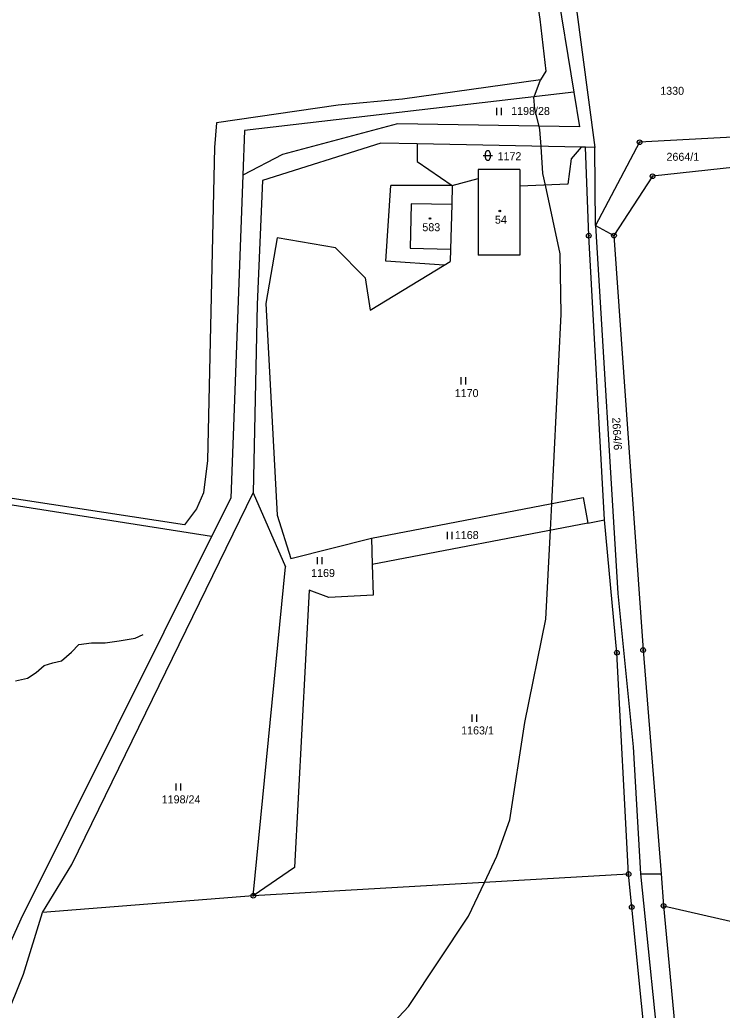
# Model space of a CAD drawing. Extents: x -439246 to -433691, y -1130252 to -1121148.
# Drawn here: x -438121.2 to -437972.2, y -1123253.1 to -1123042.9 of the extents above; entities that cross this region are included whole.
import ezdxf

# ---------------------------------------------------------------- set-up
doc = ezdxf.new("R2010")
doc.units = 0
for name, color, linetype in [('Vrstva 1', 7, 'Continuous'), ('Vrstva 18', 7, 'Continuous'), ('Vrstva 19', 7, 'Continuous'), ('Vrstva 24', 7, 'Continuous'), ('Vrstva 25', 7, 'Continuous'), ('Vrstva 3', 7, 'Continuous'), ('Vrstva 37', 7, 'Continuous'), ('Vrstva 4', 7, 'Continuous'), ('Vrstva 52', 7, 'Continuous'), ('Vrstva 6', 7, 'Continuous')]:
    doc.layers.add(name, color=color, linetype=linetype)

msp = doc.modelspace()

# ---------------------------------------------------------------- linework, layer by layer
at = {"layer": 'Vrstva 1'}
for points in [[(-438007.56, -1123034.35), (-438003.7, -1123058.22)], [(-438003.26, -1123039.6), (-437999.24, -1123069.97)], [(-438003.7, -1123058.22), (-438073.55, -1123066.39)], [(-438003.7, -1123058.22), (-438002.5, -1123065.62)], [(-438073.55, -1123066.39), (-438073.91, -1123075.87)], [(-438041.09, -1123064.97), (-438065.47, -1123071.43)], [(-438002.5, -1123065.62), (-438041.09, -1123064.97)], [(-437989.73, -1123068.85), (-437999.07, -1123086.53)], [(-437962.08, -1123067.39), (-437989.73, -1123068.85)], [(-438044.65, -1123069.05), (-438069.76, -1123077)], [(-438036.94, -1123069.21), (-438044.65, -1123069.05)], [(-438036.94, -1123069.21), (-438036.94, -1123072.93)], [(-438002.12, -1123069.91), (-438036.94, -1123069.21)], [(-438002.12, -1123069.91), (-438004.29, -1123072.36)], [(-438001.21, -1123069.93), (-438002.12, -1123069.91)], [(-438000.51, -1123088.7), (-438001.21, -1123069.93)], [(-437999.24, -1123069.97), (-438001.21, -1123069.93)], [(-437999.07, -1123086.53), (-437999.24, -1123069.97)], [(-438065.47, -1123071.43), (-438073.91, -1123075.87)], [(-438036.94, -1123072.93), (-438029.52, -1123078.04)], [(-438004.29, -1123072.36), (-438004.95, -1123077.74)], [(-438015.13, -1123074.65), (-438024.02, -1123074.65)], [(-438024.02, -1123074.65), (-438024.02, -1123076.55)], [(-438015.13, -1123074.65), (-438015.13, -1123078.21)], [(-437963.49, -1123073.53), (-437986.99, -1123076.08)], [(-438073.91, -1123075.87), (-438076.5, -1123144.41)], [(-438069.76, -1123077), (-438070.85, -1123103.32)], [(-438029.52, -1123078.04), (-438024.02, -1123076.55)], [(-438024.02, -1123076.55), (-438024.02, -1123092.83)], [(-437986.99, -1123076.08), (-437995.17, -1123088.69)], [(-438043.6, -1123094.13), (-438042.5, -1123078.06)], [(-438029.52, -1123078.04), (-438042.5, -1123078.06)], [(-438029.52, -1123078.04), (-438029.61, -1123082.11)], [(-438004.95, -1123077.74), (-438015.13, -1123078.21)], [(-438015.13, -1123078.21), (-438015.13, -1123092.83)], [(-438029.61, -1123082.11), (-438029.83, -1123091.54)], [(-438066.62, -1123089.14), (-438069.06, -1123103.08)], [(-438054.29, -1123091.3), (-438066.62, -1123089.14)], [(-437997.17, -1123149.03), (-438000.51, -1123088.7)], [(-437995.17, -1123088.69), (-437988.99, -1123176.69)], [(-438054.29, -1123091.3), (-438047.95, -1123097.67)], [(-438029.83, -1123091.54), (-438029.9, -1123094.2)], [(-438031.18, -1123094.98), (-438043.6, -1123094.13)], [(-438015.13, -1123092.83), (-438024.02, -1123092.83)], [(-438046.88, -1123104.5), (-438031.18, -1123094.98)], [(-438031.18, -1123094.98), (-438029.9, -1123094.2)], [(-438047.95, -1123097.67), (-438046.88, -1123104.5)], [(-438070.85, -1123103.32), (-438071.7, -1123143.28)], [(-438069.06, -1123103.08), (-438066.6, -1123148.04)], [(-438080.56, -1123152.59), (-438154.88, -1123140.9)], [(-438110.23, -1123222.16), (-438071.7, -1123143.28)], [(-438076.5, -1123144.41), (-438080.56, -1123152.59)], [(-438071.7, -1123143.28), (-438064.88, -1123158.97)], [(-438046.65, -1123152.95), (-438001.73, -1123144.31)], [(-438001.73, -1123144.31), (-438000.69, -1123149.71)], [(-438066.6, -1123148.04), (-438063.7, -1123157.2)], [(-438000.69, -1123149.71), (-438046.48, -1123158.51)], [(-438000.69, -1123149.71), (-437997.17, -1123149.03)], [(-437994.55, -1123177.24), (-437997.17, -1123149.03)], [(-438080.56, -1123152.59), (-438121.05, -1123233.8)], [(-438063.7, -1123157.2), (-438046.65, -1123152.95)], [(-438046.65, -1123152.95), (-438046.48, -1123158.51)], [(-438071.7, -1123228.84), (-438064.88, -1123158.97)], [(-438046.48, -1123158.51), (-438046.28, -1123165.02)], [(-438059.84, -1123163.93), (-438062.95, -1123222.85)], [(-438055.66, -1123165.52), (-438059.84, -1123163.93)], [(-438046.28, -1123165.02), (-438055.66, -1123165.52)], [(-437992.08, -1123224.24), (-437994.55, -1123177.24)], [(-437988.99, -1123176.69), (-437985.19, -1123224.15)], [(-438116.42, -1123232.41), (-438110.23, -1123222.16)], [(-438062.95, -1123222.85), (-438071.7, -1123228.84)], [(-437992.08, -1123224.24), (-438071.7, -1123228.84)], [(-437991.41, -1123231.23), (-437992.08, -1123224.24)], [(-437985.19, -1123224.15), (-437984.64, -1123230.98)], [(-438071.7, -1123228.84), (-438116.42, -1123232.41)], [(-438120.43, -1123245.5), (-438116.42, -1123232.41)], [(-437983.13, -1123313.75), (-437991.41, -1123231.23)], [(-437984.64, -1123230.98), (-437976.9, -1123313.79)], [(-437984.64, -1123230.98), (-437957.14, -1123237.29)], [(-438121.05, -1123233.8), (-438129.19, -1123251.89)], [(-438124.36, -1123255.18), (-438120.43, -1123245.5)]]:
    msp.add_lwpolyline(points, dxfattribs=at)
at = {"layer": 'Vrstva 24'}
for centre, radius in [((-437989.73, -1123068.85), 0.5), ((-437989.73, -1123068.85), 0.1), ((-437986.99, -1123076.08), 0.5), ((-437986.99, -1123076.08), 0.1), ((-438000.51, -1123088.7), 0.5), ((-438000.51, -1123088.7), 0.1), ((-437995.17, -1123088.69), 0.5), ((-437995.17, -1123088.69), 0.1), ((-437994.55, -1123177.24), 0.5), ((-437994.55, -1123177.24), 0.1), ((-437988.99, -1123176.69), 0.5), ((-437988.99, -1123176.69), 0.1), ((-437992.08, -1123224.24), 0.5), ((-437992.08, -1123224.24), 0.1), ((-438071.7, -1123228.84), 0.5), ((-438071.7, -1123228.84), 0.1), ((-437991.41, -1123231.23), 0.5), ((-437984.64, -1123230.98), 0.5), ((-437991.41, -1123231.23), 0.1), ((-437984.64, -1123230.98), 0.1)]:
    msp.add_circle(centre, radius, dxfattribs=at)
at = {"layer": 'Vrstva 25'}
for p, q in [((-438020.02, -1123063.08), (-438020.02, -1123061.58)), ((-438019.02, -1123063.08), (-438019.02, -1123061.58)), ((-438022.96, -1123071.68), (-438020.96, -1123071.68)), ((-438022.46, -1123072.18), (-438022.46, -1123071.18)), ((-438021.46, -1123071.18), (-438021.46, -1123072.18)), ((-438027.63, -1123120.27), (-438027.63, -1123118.77)), ((-438026.63, -1123120.27), (-438026.63, -1123118.77)), ((-438030.47, -1123153.1), (-438030.47, -1123151.6)), ((-438029.47, -1123153.1), (-438029.47, -1123151.6)), ((-438058.11, -1123158.46), (-438058.11, -1123156.96)), ((-438057.11, -1123158.46), (-438057.11, -1123156.96)), ((-438025.29, -1123191.88), (-438025.29, -1123190.38)), ((-438024.29, -1123191.88), (-438024.29, -1123190.38)), ((-438088.04, -1123206.52), (-438088.04, -1123205.02)), ((-438087.04, -1123206.52), (-438087.04, -1123205.02))]:
    msp.add_line(p, q, dxfattribs=at)
for centre in [(-438019.39, -1123083.45), (-438034.21, -1123085.05)]:
    msp.add_circle(centre, 0.175, dxfattribs=at)
for centre, start, end in [((-438021.96, -1123071.18), 0, 180), ((-438021.96, -1123072.18), 180, 0)]:
    msp.add_arc(centre, 0.5, start, end, dxfattribs=at)
at = {"layer": 'Vrstva 3'}
for points in [[(-438015.13, -1123074.65), (-438024.02, -1123074.65)], [(-438024.02, -1123074.65), (-438024.02, -1123076.55)], [(-438015.13, -1123074.65), (-438015.13, -1123078.21)], [(-438024.02, -1123076.55), (-438024.02, -1123092.83)], [(-438015.13, -1123078.21), (-438015.13, -1123092.83)], [(-438038.22, -1123081.91), (-438038.44, -1123091.34)], [(-438029.61, -1123082.11), (-438038.22, -1123081.91)], [(-438029.61, -1123082.11), (-438029.83, -1123091.54)], [(-438038.44, -1123091.34), (-438029.83, -1123091.54)], [(-438015.13, -1123092.83), (-438024.02, -1123092.83)]]:
    msp.add_lwpolyline(points, dxfattribs=at)
at = {"layer": 'Vrstva 37'}
for centre in [(-438019.39, -1123083.45), (-438034.21, -1123085.05)]:
    msp.add_circle(centre, 0.175, dxfattribs=at)
at = {"layer": 'Vrstva 4'}
for points in [[(-438038.22, -1123081.91), (-438038.44, -1123091.34)], [(-438029.61, -1123082.11), (-438038.22, -1123081.91)], [(-438038.44, -1123091.34), (-438029.83, -1123091.54)], [(-438096.78, -1123174.17), (-438095.03, -1123173.38)], [(-438110.25, -1123177.13), (-438108.73, -1123175.5)], [(-438108.73, -1123175.5), (-438106.01, -1123175.16)], [(-438106.01, -1123175.16), (-438103.14, -1123175.16)], [(-438103.14, -1123175.16), (-438100.13, -1123174.69)], [(-438100.13, -1123174.69), (-438096.78, -1123174.17)], [(-438112.41, -1123178.99), (-438110.25, -1123177.13)], [(-438117.75, -1123181.46), (-438116.05, -1123179.92)], [(-438116.05, -1123179.92), (-438114.2, -1123179.4)], [(-438114.2, -1123179.4), (-438112.41, -1123178.99)], [(-438119.61, -1123182.61), (-438117.75, -1123181.46)], [(-438122.14, -1123183.19), (-438119.61, -1123182.61)]]:
    msp.add_lwpolyline(points, dxfattribs=at)
at = {"layer": 'Vrstva 52'}
for points in [[(-438043.8, -1122847.97), (-438041.99, -1122856.04), (-438041.99, -1122859.45), (-438039.43, -1122869.67), (-438026.86, -1122932.75), (-438025.58, -1122944.68), (-438023.24, -1122957.46), (-438022.39, -1122967.69), (-438020.55, -1122978.34), (-438018.12, -1122992.41), (-438017.27, -1123001.78), (-438010.88, -1123042.7), (-438009.6, -1123053.78), (-438010.76, -1123055.63)], [(-438010.76, -1123055.63), (-438040.07, -1123059.74), (-438053.71, -1123061.02), (-438079.52, -1123064.74), (-438079.92, -1123069.97), (-438081.41, -1123136.45), (-438082.26, -1123143.27), (-438083.75, -1123146.68), (-438086.31, -1123150.09), (-438285.73, -1123119.57), (-438288.69, -1123119.01), (-438294.49, -1123117.91), (-438293.64, -1123112.59), (-438295.13, -1123111.09), (-438295.34, -1123110.88), (-438339.66, -1123107.84), (-438392.93, -1123104.49), (-438396.76, -1123103.64), (-438423.19, -1123101.72), (-438446.64, -1123100.23)], [(-438008.39, -1123145.59), (-438006.41, -1123105.34), (-438006.62, -1123092.56), (-438009.72, -1123077.96), (-438010.24, -1123075.51), (-438010.63, -1123069.74), (-438010.88, -1123066.13), (-438011.04, -1123065.47), (-438011.94, -1123061.87), (-438012.16, -1123059.32), (-438012.11, -1123059.2), (-438010.76, -1123055.63)], [(-438138.51, -1123324.17), (-438119.69, -1123312.12), (-438114.25, -1123308.63), (-438111.24, -1123306.7), (-438104.42, -1123301.59), (-438096.13, -1123296.87), (-438092.01, -1123294.52), (-438089.08, -1123292.85), (-438077.15, -1123284.75), (-438048.17, -1123262.38), (-438038.79, -1123252.37), (-438026.01, -1123233.19), (-438022.66, -1123226.01), (-438020.04, -1123220.4), (-438017.27, -1123212.73), (-438014.07, -1123192.06), (-438009.6, -1123170.12), (-438008.67, -1123151.24), (-438008.39, -1123145.59)]]:
    msp.add_lwpolyline(points, dxfattribs=at)
at = {"layer": 'Vrstva 6'}
for points in [[(-437999.07, -1123086.53), (-437995.17, -1123088.69)], [(-437999.07, -1123086.53), (-437994.36, -1123164.66)], [(-437994.36, -1123164.66), (-437991.07, -1123197.22)], [(-437991.07, -1123197.22), (-437989.54, -1123224.15)], [(-437989.54, -1123224.15), (-437985.19, -1123224.15)], [(-437989.54, -1123224.15), (-437980.36, -1123314.21)]]:
    msp.add_lwpolyline(points, dxfattribs=at)

# ---------------------------------------------------------------- texts
at = {"layer": 'Vrstva 18'}
for s, p in [('1330', (-437985.36, -1123058.79)), ('1198/28', (-438016.99, -1123063.08)), ('1172', (-438019.88, -1123072.68)), ('2664/1', (-437984.04, -1123072.8)), ('1170', (-438028.96, -1123122.97)), ('1168', (-438028.94, -1123153.1)), ('1169', (-438059.43, -1123161.16)), ('1163/1', (-438027.6, -1123194.58)), ('1198/24', (-438091.13, -1123209.22))]:
    msp.add_text(s, height=1.7, dxfattribs=at).set_placement(p)
msp.add_text('2664/6', height=1.7, rotation=273.1123, dxfattribs=at).set_placement((-437995.56, -1123127.33))
at = {"layer": 'Vrstva 19'}
for s, p in [('54', (-438020.43, -1123086.15)), ('583', (-438035.83, -1123087.75))]:
    msp.add_text(s, height=1.7, dxfattribs=at).set_placement(p)

doc.saveas('drawing.dxf')
